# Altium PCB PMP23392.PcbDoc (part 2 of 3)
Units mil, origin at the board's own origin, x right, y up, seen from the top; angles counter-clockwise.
Board outline 5000 x 3400 mil, 6 copper layers (Top Layer, Midlayer 1, Midlayer 2, Midlayer 3, Midlayer 4, Bottom Layer), stack 61.536 mil thick; 247 components, 68 nets, 546 pads, 871 vias.
Unrouted connection lines stored in the file: 21.
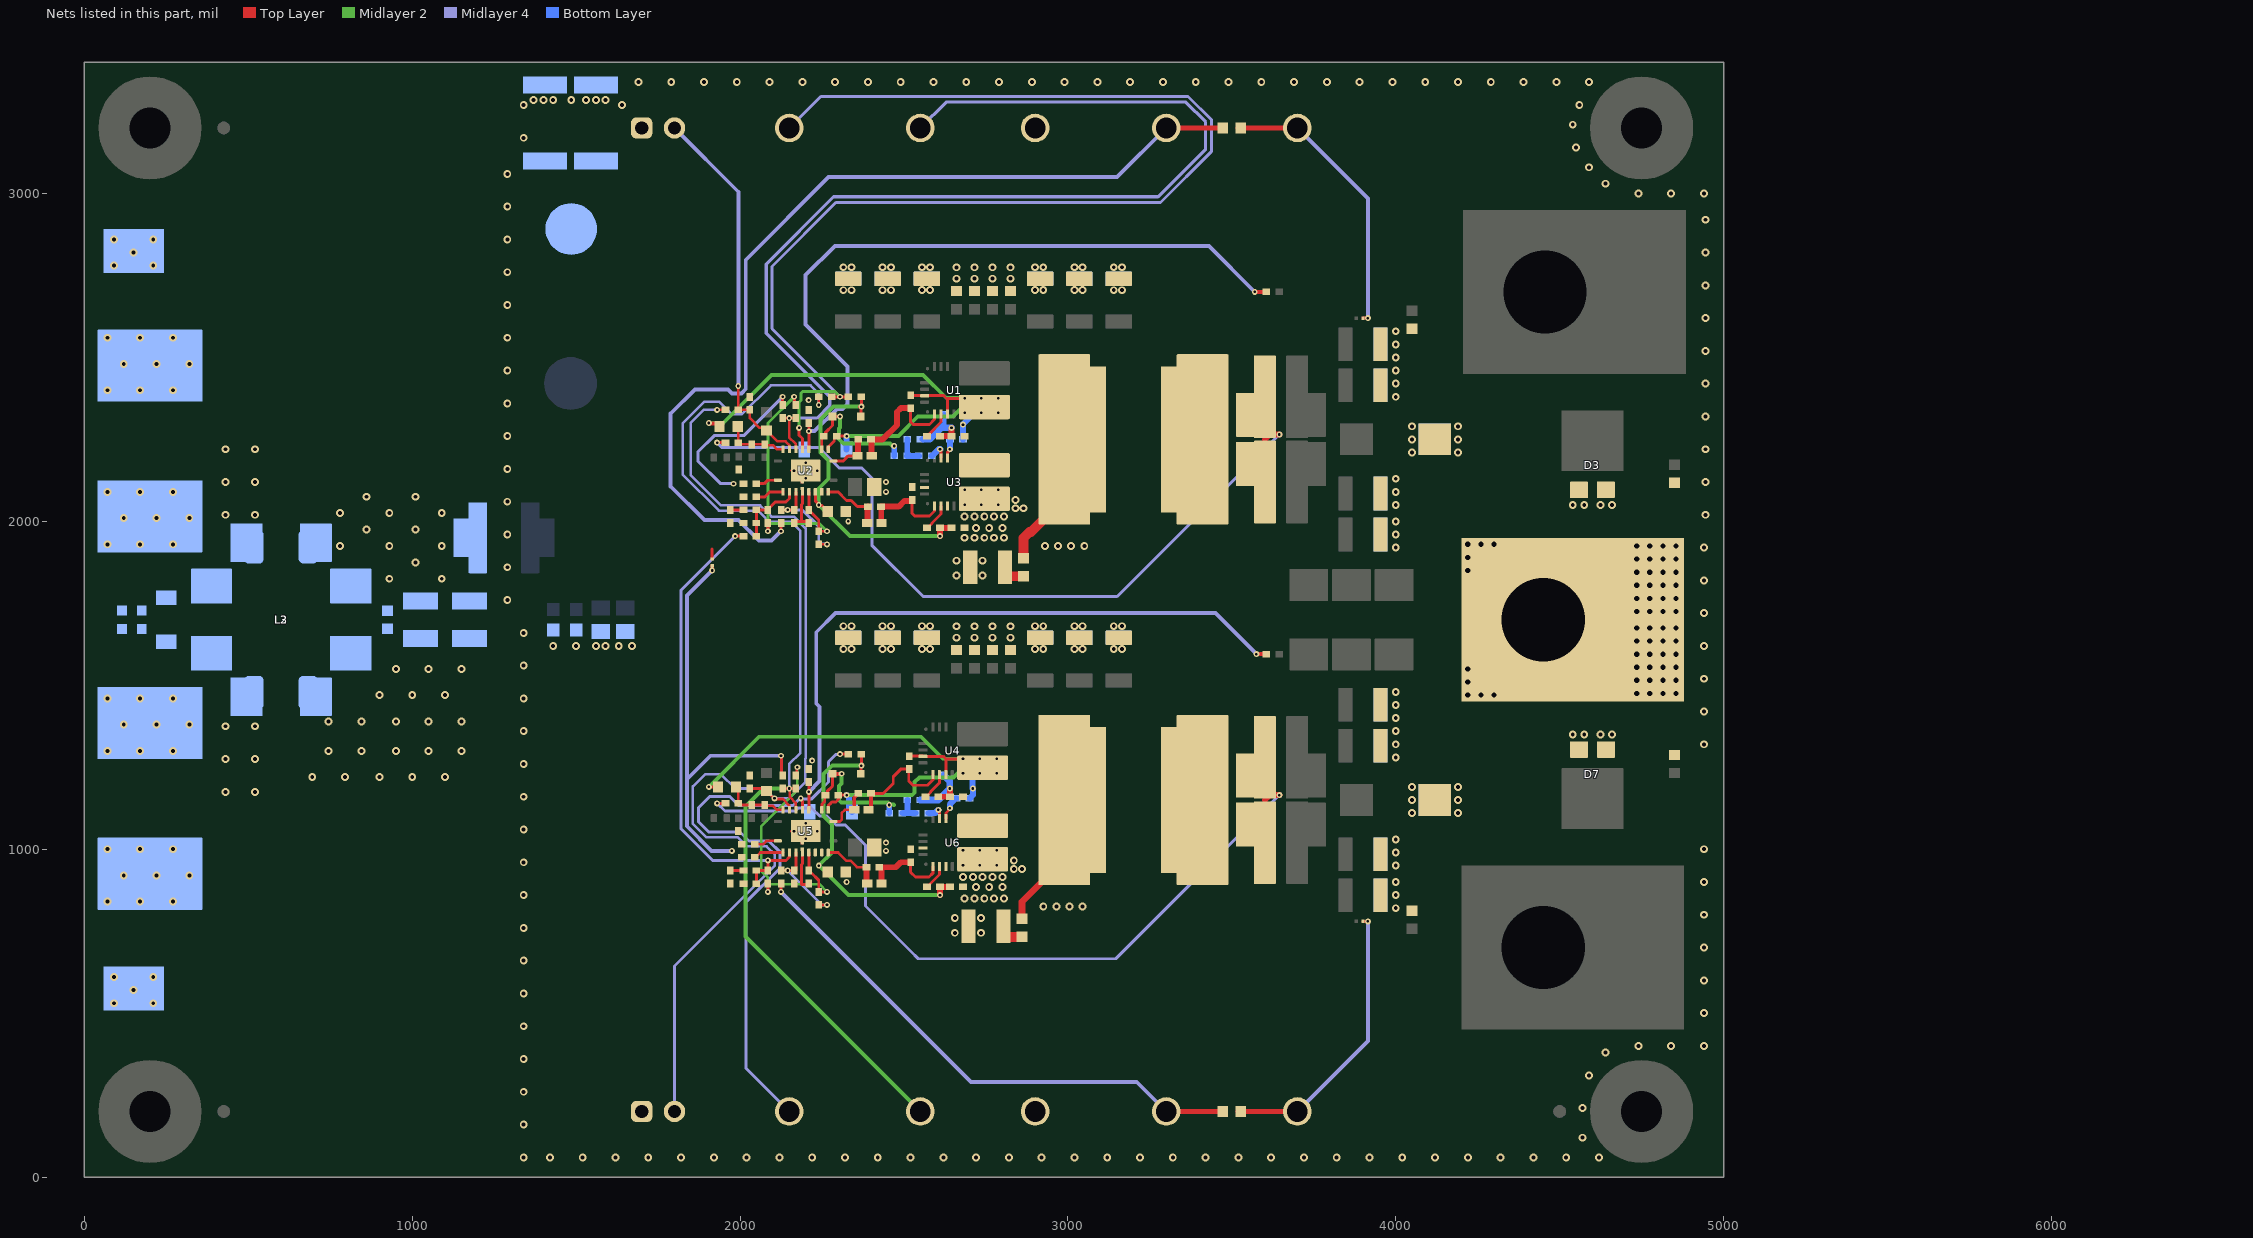
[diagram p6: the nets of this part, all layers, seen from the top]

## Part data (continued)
C52: library part CMP-0006353-2, "CAP, CERM, 0.022 uF, 25 V, +/- 10%, X7R, AEC-Q200 Grade 1, 0402", Cap_Case=0402, Manufacturer=MuRata, Supplier Part Number 1=490-6044-1-ND, TempCo=X7R, Tolerance_%=10%, Value1=Unknown, Value2=25V, ValueDisplayed=0.022uF
C53 C95: library part CMP-0006705-2, "CAP, CERM, 270 pF, 100 V, +/- 10%, X7R, 0402", Cap_Case=0402, Manufacturer=MuRata, Supplier Part Number 1=GRM155R72A271KA01D-ND, TempCo=X7R, Tolerance_%=10%, Value1=Unknown, Value2=100V, ValueDisplayed=270pF
C94: library part CMP-0006670-2, "CAP, CERM, 5600 pF, 25 V, +/- 10%, X7R, 0402", Cap_Case=0402, Manufacturer=MuRata, PartNumber=GRM155R71E562KA01D, Supplier Part Number 1=490-5420-1-ND, TempCo=X7R, Tolerance_%=10%, Value1=Unknown, Value2=25V, ValueDisplayed=5600pF
C96 C97 C98 C99: library part CMP-0025958-3, "RES, 10.0 k, 1%, 0.063 W, AEC-Q200 Grade 0, 0402", Manufacturer=Vishay-Dale, Power_W=63mW, Supplier Part Number 1=541-10.0KLCT-ND, TempCo="100 ppm/C", Tolerance_%=1%, Value2=0.063W, Value_Code=10k0, ValueDisplayed=10.0k
D1 D5: library part CMP-0076946-1, "Diode, Schottky, 100 V, 0.25 A, SOD-323F", Manufacturer=Nexperia, Supplier Part Number 1=568-6017-1-ND, Value1=0.25A, Value2=0.85V
D2 D6: library part Zener, "Diode, Zener, 5.6V, 2%, 500mW, SOD-323F", Alternate Manufacturer=-, Manufacturer=Nexperia
D3 D7: library part CMP-0048085-1, "Diode 40 V 10A Surface Mount TO-277A (SMPC)", Digikey Part Number=SS10P4HM3_A/HGICT-ND, Forward Current=10A, Manufacturer=Vishay, Max Surge Forward Current=280A, Mouser Part Number=78-SS10P4HM3_A/H, Operating Temperature Range="-55°C to +150°C", Peak Reverse Current=100uA, ValueDisplayed=750pF
D4 D8: library part Diode_Schottky, "Diode, Schottky, 100V, 2A, SOD-123", Alternate Manufacturer=-, Manufacturer=Nexperia, PartNumber=PMEG10020AELRX
D9 D10 D11 D12: library part Diode_Schottky, "Diode, Schottky, 30V, 200mA, SOD-523", Alternate Manufacturer=-, Manufacturer="ON Semi", PartNumber=NSVRB521S30T1G
FID1 FID2 FID3 FID4 FID5 FID6: library part CMP-0077181-1, "Fiducial mark.  There is nothing to buy or mount.", Manufacturer=N/A
H1 H2 H3 H4: library part CMP-0003617-1, "Machine Screw, Round, #4-40 x 1/4, Nylon, Philips panhead", Manufacturer="B&F Fastener Supply", Supplier Part Number 1=H542-ND
H5 H6 H7 H8: library part CMP-0003610-1, "Standoff, Hex, 0.5\"L #4-40 Nylon", Manufacturer=Keystone, Supplier Part Number 1=36-1902C-ND
J1 J2 J7 J9 J10 J11: library part CMP-0055135-1, "Shorting Jumper, 5.375mm, 2 Position, Tin, SMT", Color=Silver, Manufacturer=Keystone, PartNumber=5102, Supplier Part Number 1=36-5102-ND
J3 J4: library part CMP-0079575-1, "Banana Jack Insul Nylon Red, TH", Color=Red, Current_A=15A, Manufacturer="Cinch Connectivity", PartNumber=108-0902-001, Supplier Part Number 1=J151-ND
J5 J6: library part CMP-0079574-1, "Banana Jack Insul Nylon Black, TH", Color=Black, Current_A=15A, Manufacturer="Cinch Connectivity", PartNumber=108-0903-001, Supplier Part Number 1=J152-ND
J8 J12: library part CMP-0075405-3, "Header, 100mil, 2x1, Gold, TH", Color=Black, Current_A=6.3A, Manufacturer=Samtec, PartNumber=TSW-102-07-G-S, Supplier Part Number 1=SAM1029-02-ND, Voltage_V=550V
L1: library part CMP-0048360-1, "1 µH Shielded Molded Inductor 22 A 2.9mOhm Max Nonstandard", Digikey Part Number=2457-XGL6060-102MEC-ND, Manufacturer=Coilcraft, Operating Temperature Range=to, Part Number=XGL6060-102MEC, Self Resonant Frequency=46MHz, Test Frequency=1MHz, Tolerance_%=20%
L2: library part CMP-0084691-1, "Coupled inductor,  ohm, AEC-Q200 Grade 1, SMD", Manufacturer=TDK, PartNumber=ACM12V-701-2PL-TL00
L3: library part CMP-0013197-2, "Coupled inductor, 2 uH,  A, 1.8 ohm, SMD", Manufacturer=MuRata, PartNumber=PLT10HH101150PNL, Supplier Part Number 1=490-12821-1-ND, ValueDisplayed=2uH
L4 L6: library part CMP-0060945-1, "Inductor, Shielded, Composite, 1.5 uH, 36.6 A, 0.0016 ohm, SMD", Manufacturer=Coilcraft, Value1="0.0016 ohm", Value2=36.6A, ValueDisplayed=1.5uH
L5 L7: library part CMP-0047844-1, "Power Choke Coil 2.5uH 20% 100kHz 2.53mOhm 32A AECQ200 13.3x12.8x8.0mm SMT", Manufacturer=CYNTEC, Operating Temperature Range="-55°C to +180°C", Part Number=VCUD128T-2R5MS8, Test Frequency=100kHz, Tolerance_%=20%
LBL1: library part CMP-0003625-1, "Thermal Transfer Printable Labels, 0.650\" W x 0.200\" H - 10,000 per roll", Manufacturer=Brady, Supplier Part Number 1=97C5133
Logo1: library part CMP-0074844-1
Logo2: library part CMP-0074847-1, "FCC_disclaimer"
Logo3: library part CMP-0074769-1
NT1 NT2 NT3 NT4 NT5: library part CMP-0078142-3, "Single point connection between nets.", Manufacturer=N/A
R1 R2: library part CMP-0015904-3, "RES, 1.0, 5%, 1 W, AEC-Q200 Grade 0, 2512", Manufacturer=Vishay-Dale, Power_W=1W, Supplier Part Number 1=541-1.0XCT-ND, TempCo="200 ppm/C", Tolerance_%=5%, Value_Code=1R00, ValueDisplayed=1.0
R3 R4 R7 R21 R27 R28 R31 R32 R43 R47 R49: library part CMP-0081856-1, "RES, 0, 0%, 0.2 W, AEC-Q200 Grade 0, 0402", Manufacturer=Vishay-Dale, Power_W=200mW, Supplier Part Number 1=541-0.0YBTR-ND, Tolerance_%=0%, Value2=0.2W, Value_Code=0
R5 R30 R66 R67: library part CMP-0046355-1, "Res Current Sense Thick Film 1225 0.5m Ohm 5% 2W ±150ppm/°C Molded Emboss T/R", Digikey Part Number=RHM.0005BRCT-ND, Manufacturer="Rohm Semiconductor", Mouser Part Number=755-PML100HZPJV0L5, Operating Temperature Range="-55°C to +155°C", Part Number=PML100HZPJV0L5, Power_W=2W, TempCo=150ppm/°C, Tolerance_%=5%
R6: library part CMP-0022060-4, "RES, 150 k, 1%, 0.1 W, AEC-Q200 Grade 0, 0603", Manufacturer=Vishay-Dale, Power_W=100mW, Supplier Part Number 1=541-150KHCT-ND, TempCo="100 ppm/C", Tolerance_%=1%, Value2=0.1W, Value_Code=150k
R8 R33: library part CMP-0001672-1, "1.2 mOhms ±1% 5W Chip Resistor 2512 (6432 Metric) Automotive AEC-Q200, Current Sense, Non-Inductive Metal Element", Digikey Part Number=804-Y14830R00120F9RCT-ND, Manufacturer="Vishay Foil Resistors", Operating Temperature Range="-65°C to +170°C", Power_W=5W, Tolerance_%=1%
R9: library part CMP-0026517-2, "RES, 6.81 k, 1%, 0.063 W, AEC-Q200 Grade 0, 0402", Manufacturer=Vishay-Dale, Power_W=63mW, Supplier Part Number 1=541-6.81KLCT-ND, TempCo="100 ppm/C", Tolerance_%=1%, Value2=0.063W, Value_Code=6k81, ValueDisplayed=6.81k
R10 R19 R46 R50: library part CMP-0026753-1, "RES, 100 k, 1%, 0.063 W, AEC-Q200 Grade 0, 0402", Manufacturer="Stackpole Electronics Inc", PartNumber=RMCF0402FT100K, Power_W=63mW, Supplier Part Number 1=RMCF0402FT100KCT-ND, TempCo="100 ppm/C", Tolerance_%=1%, Value2=0.063W, Value_Code=100k
R11 R16 R36 R41: library part Resistor, "RES, xxx ohm, x%, xW, [PackageReference]", Alternate Manufacturer=-, Manufacturer="Used in BOM report"
R12 R37: library part CMP-0026404-2, "RES, 49.9, 1%, 0.063 W, AEC-Q200 Grade 0, 0402", Manufacturer=Vishay-Dale, Power_W=63mW, Supplier Part Number 1=541-49.9LCT-ND, TempCo="100 ppm/C", Tolerance_%=1%, Value2=0.063W, Value_Code=49R9, ValueDisplayed=49.9
R13 R38: library part CMP-0086542-2, "RMCF/RMCP Series General Purpose Thick Film Standard Power and High Power Chip Resistor", Manufacturer=Stackpole, TempCo=-, Value1=0
R14 R39: library part Resistor, "RES, 1.0 ohm, 5%, 0.5W, 1210", Alternate Manufacturer=-, Manufacturer=Stackpole, PartNumber=RMCF1210JT4R70
R15 R20 R40 R45 R58 R59 R60 R61 R62 R63: library part CMP-0081856-1, "RES, 0, 0%, 0.2 W, AEC-Q200 Grade 0, 0402", Manufacturer=Vishay-Dale, PartNumber=CRCW04020000Z0EDHP, Power_W=200mW, Supplier Part Number 1=541-0.0YBTR-ND, Tolerance_%=0%, Value2=0.2W, Value_Code=0
R17: library part CMP-0022448-4, "RES, 49.9, 1%, 0.1 W, AEC-Q200 Grade 0, 0603", Manufacturer=Vishay-Dale, Power_W=100mW, Supplier Part Number 1=541-49.9HCT-ND, TempCo="100 ppm/C", Tolerance_%=1%, Value2=0.1W, Value_Code=49R9, ValueDisplayed=49.9
R18 R44: library part CMP-0026539-2, "RES, 73.2 k, 1%, 0.063 W, AEC-Q200 Grade 0, 0402", Manufacturer=Vishay-Dale, Power_W=63mW, Supplier Part Number 1=541-73.2KLCT-ND, TempCo="100 ppm/C", Tolerance_%=1%, Value2=0.063W, Value_Code=73k2, ValueDisplayed=73.2k
R22: library part CMP-0026399-2, "RES, 48.7 k, 1%, 0.063 W, AEC-Q200 Grade 0, 0402", Manufacturer=Vishay-Dale, PartNumber=CRCW040248K7FKED, Power_W=63mW, Supplier Part Number 1=541-48.7KLCT-ND, TempCo="100 ppm/C", Tolerance_%=1%, Value2=0.063W, Value_Code=48k7, ValueDisplayed=48.7k
R23 R35: library part CMP-0026753-1, "RES, 100 k, 1%, 0.063 W, AEC-Q200 Grade 0, 0402", Manufacturer="Stackpole Electronics Inc", Power_W=63mW, Supplier Part Number 1=RMCF0402FT100KCT-ND, TempCo="100 ppm/C", Tolerance_%=1%, Value2=0.063W, Value_Code=100k
R24: library part CMP-0026329-2, "RES, 3.01 k, 1%, 0.063 W, AEC-Q200 Grade 0, 0402", Manufacturer=Vishay-Dale, Power_W=63mW, Supplier Part Number 1=541-3.01KLCT-ND, TempCo="100 ppm/C", Tolerance_%=1%, Value2=0.063W, Value_Code=3k01, ValueDisplayed=3.01k
R25: library part CMP-0026449-2, "RES, 54.9 k, 1%, 0.063 W, AEC-Q200 Grade 0, 0402", Manufacturer=Vishay-Dale, Power_W=63mW, Supplier Part Number 1=541-54.9KLCT-ND, TempCo="100 ppm/C", Tolerance_%=1%, Value2=0.063W, Value_Code=54k9, ValueDisplayed=54.9k
R26: library part CMP-0026067-3, "RES, 19.1 k, 1%, 0.063 W, AEC-Q200 Grade 0, 0402", Manufacturer=Vishay-Dale, Power_W=63mW, Supplier Part Number 1=541-19.1KLCT-ND, TempCo="100 ppm/C", Tolerance_%=1%, Value2=0.063W, Value_Code=19k1, ValueDisplayed=19.1k
R29: library part CMP-0021990-4, "RES, 100 k, 1%, 0.1 W, AEC-Q200 Grade 0, 0603", Manufacturer=Vishay-Dale, PartNumber=CRCW0603100KFKEA, Power_W=100mW, Supplier Part Number 1=541-100KHCT-ND, TempCo="100 ppm/C", Tolerance_%=1%, Value2=0.1W, Value_Code=100k
R34: library part CMP-0026412-2, "RES, 4.75 k, 1%, 0.063 W, AEC-Q200 Grade 0, 0402", Manufacturer=Vishay-Dale, PartNumber=CRCW04024K75FKED, Power_W=63mW, Supplier Part Number 1=541-4.75KLCT-ND, TempCo="100 ppm/C", Tolerance_%=1%, Value2=0.063W, Value_Code=4k75, ValueDisplayed=4.75k
R42: library part CMP-0022448-4, "RES, 49.9, 1%, 0.1 W, AEC-Q200 Grade 0, 0603", Manufacturer=Vishay-Dale, PartNumber=CRCW060349R9FKEA, Power_W=100mW, Supplier Part Number 1=541-49.9HCT-ND, TempCo="100 ppm/C", Tolerance_%=1%, Value2=0.1W, Value_Code=49R9, ValueDisplayed=49.9
R48: library part CMP-0026555-2, "RES, 7.50 k, 1%, 0.063 W, AEC-Q200 Grade 0, 0402", Manufacturer=Vishay-Dale, PartNumber=CRCW04027K50FKED, Power_W=63mW, Supplier Part Number 1=541-7.50KLCT-ND, TempCo="100 ppm/C", Tolerance_%=1%, Value2=0.063W, Value_Code=7k50, ValueDisplayed=7.50k
R51 R53: library part CMP-0086542-2, "RMCF/RMCP Series General Purpose Thick Film Standard Power and High Power Chip Resistor", Manufacturer=Stackpole, PartNumber=RMCF0402ZT0R00, TempCo=-
R52: library part CMP-0026605-2, "RES, 90.9 k, 1%, 0.063 W, AEC-Q200 Grade 0, 0402", Manufacturer=Vishay-Dale, Power_W=63mW, Supplier Part Number 1=541-90.9KLCT-ND, TempCo="100 ppm/C", Tolerance_%=1%, Value2=0.063W, Value_Code=90k9, ValueDisplayed=90.9k
R54 R55 R56 R57: library part CMP-0026357-2, "RES, 3.32, 1%, 0.063 W, AEC-Q200 Grade 0, 0402", Manufacturer=Vishay-Dale, Power_W=63mW, Supplier Part Number 1=541-3.32LLCT-ND, TempCo="100 ppm/C", Tolerance_%=1%, Value2=0.063W, Value_Code=3R32, ValueDisplayed=3.32
R64 R65: library part CMP-0001672-1, "1.2 mOhms ±1% 5W Chip Resistor 2512 (6432 Metric) Automotive AEC-Q200, Current Sense, Non-Inductive Metal Element", Digikey Part Number=804-Y14830R00120F9RCT-ND, Manufacturer="Vishay Foil Resistors", Operating Temperature Range="-65°C to +170°C", Part Number=Y14830R00120F9R, Power_W=5W, Tolerance_%=1%
SH-J1 SH-J2: library part CMP-0003761-2, "Shunt, 2.54mm, Gold, Black", Manufacturer="Wurth Elektronik", Supplier Part Number 1=732-2678-ND
T1 T2 T3: library part CMP-0055443-2, "Terminal 90A Lug", Manufacturer=Panduit, PartNumber=CB70-14-CY, Supplier Part Number 1=CB70-14-CY-ND, Voltage_V=600V
TP1 TP2: library part CMP-0055153-2, "Test Point, Compact, SMT", Manufacturer="Keystone Electronics", PartNumber=5016, Supplier Part Number 1=36-5016TR-ND
TP3 TP9: library part CMP-0055147-1, "Test Point, Multipurpose, Red, TH", Color=Red, Manufacturer=Keystone, PartNumber=5010, Supplier Part Number 1=36-5010-ND
TP4 TP5 TP6 TP10 TP11 TP12: library part CMP-0055149-1, "Test Point, Multipurpose, White, TH", Color=White, Manufacturer=Keystone, PartNumber=5012, Supplier Part Number 1=36-5012-ND
TP7 TP8: library part CMP-0055148-1, "Test Point, Multipurpose, Black, TH", Color=Black, Manufacturer=Keystone, PartNumber=5011, Supplier Part Number 1=36-5011-ND
U1 U3 U4 U6: library part CMP-0037654-1, "100-V, 64-A GaN with Integrated Driver", Manufacturer="Texas Instruments", Max Supply Voltage=5.25V, Min Supply Voltage=4.75V, Nominal Supply Current=3mA, Operating Temperature Range="-40°C to +125°C"
U2 U5: library part CMP-0120564-1, "80-V, Automotive, Synchronous, Buck DC/DC Controller with Ultra-Low IQ and Dual Random Spread Spectrum", Manufacturer="Texas Instruments", Max Supply Voltage=80V, Min Supply Voltage=3.5V, Nominal Supply Current=9.5-124uA, Operating Temperature Range="-40°C to +150°C", Output Voltage=3.3/5/12/0.8-55V, Switching Frequency=0.1-2.2MHz

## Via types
v1: diameter 24, hole 12, Top Layer to Bottom Layer, tented both sides, 526 vias
v2: diameter 32, hole 16, Top Layer to Bottom Layer, 174 vias
v3: diameter 18, hole 8, Top Layer to Bottom Layer, tented both sides, 77 vias
v4: diameter 24, hole 12, Top Layer to Bottom Layer, 46 vias
v5: diameter 19.68, hole 7.87, Top Layer to Bottom Layer, tented both sides, 44 vias
v6: diameter 19.68, hole 7.87, Top Layer to Bottom Layer, tented bottom, 4 vias

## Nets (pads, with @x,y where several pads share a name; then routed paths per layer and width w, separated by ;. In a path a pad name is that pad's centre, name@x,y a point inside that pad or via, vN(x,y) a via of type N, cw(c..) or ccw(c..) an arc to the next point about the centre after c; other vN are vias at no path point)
+Filter: C5.2 C6.2 C7.1 J1.2 J2.1 L1.2 L2.3 L3.3
  other v1: 930,1825 1090,1825 1010,1875 780,1925 930,1925 1090,1925 860,1975 1010,1975 780,2025 930,2025 1090,2025 860,2075 1010,2075
+Vin_Main: C2.1 C3.1 C4.1 J2.2 J3.1 J4.1 L2.2 L3.4 TP1.1
  other v1: 430,2020 520,2020 430,2120 520,2120 430,2220 520,2220
  other v4: 70,1930 170,1930 270,1930 120,2010 220,2010 320,2010 70,2090 170,2090 270,2090 70,2400 170,2400 270,2400 120,2480 220,2480 320,2480 70,2560 170,2560 270,2560 90,2780 210,2780 150,2820 90,2860 210,2860
AGND1: C33.1 C51.2 C52.2 NT2.2 NT3.1 R18.2 R20.2 R25.1 R26.1 U2.5 | length 689.6
  Top Layer w9: NT3.1@1915,1885 1915,1915.76 ; R20.2@2130,2354.69 v3(2130,2380) ; R26.1@2165,1995.32 2169.96,2000.27 2187.22,2000.27 ; U2.5@2190.16,2090.04 2190.16,2054 2187.22,2051.05 2187.22,2000.27 ; C33.1@2210,1995.32 2205.04,2000.27 2187.22,2000.27
  Midlayer 4 w9: v3(1980.16,2114.84) 1940.75,2114.84 1871.25,2184.34 1871.25,2211.48 1921.15,2261.37 2011.37,2261.37 v3(2130,2380)
AGND2: C75.1 C93.2 C94.2 NT3.2 NT5.2 R44.2 R45.2 R52.1 R53.2 U5.5 | length 1496.5
  Top Layer w9: v3(2125,1285) 2126.72,1283.28 2126.72,1227.96 R45.2@2130,1224.69 ; U5.5@2190.16,990.04 2190.16,955.73 2187.22,952.79 2187.22,892.26 2205.22,892.26 C75.1@2209.69,896.73
  Top Layer w10: v3(1915,1850) NT3.2@1915,1865
  Midlayer 4 w12: v3(1915,1850) 1838.37,1773.37 1838.37,1213.37 ; v3(1975,995) 1913.33,995 1838.37,1069.96 1838.37,1213.37 ; v3(2125,1285) 1910,1285 1838.37,1213.37
Bode1: R17.1 R23.2 TP6.1 | length 2958
  Top Layer w9: v3(2125,1970) R23.2@2125,1995.31
  Top Layer w16: TP6.1@3300,3200 R17.1@3480.31,3200
  Midlayer 4 w12: v3(2125,1970) 2096.22,1941.22 2057.56,1941.22 1994.57,2004.21 1891.24,2004.21 1788.46,2106.99 1788.46,2328.46 1862.61,2402.61 1963.37,2402.61 1975.98,2390 2004.04,2390 2017.44,2403.4 2017.44,2797.44 2270,3050 3150,3050 TP6.1@3300,3200
Bode2: R42.1 R50.2 TP12.1 | length 1658.2
  Top Layer w9: v3(2125,870) R50.2@2125,895.31
  Top Layer w16: TP12.1@3300,200 R42.1@3480.31,200
  Midlayer 4 w12: v3(2125,870) 2705,290 3210,290 TP12.1@3300,200
CNFG1: R25.2 U2.1 | length 70
  Top Layer w9: R25.2@2049.69,2115 2073.69,2115 2084.16,2125.47 U2.1@2115.35,2125.47
CNFG2: R52.2 U5.1 | length 75
  Top Layer w8: R52.2@2044.69,1015 2070,1015 2080.47,1025.47 U5.1@2115.35,1025.47
COMP1: C51.1 R19.1 R24.2 R49.2 U2.3 | length 217.1
  Top Layer w9: R49.2@2049.69,1955 C51.1@2049.68,1995 R24.2@2049.69,2035 2049.84,2034.84 2084.84,2034.84 R19.1@2085,2034.68 2085,2036.65 2107.22,2058.87 2139.66,2058.87 2150.79,2070 U2.3@2150.79,2090.04
COMP2: C93.1 R46.2 R48.2 R49.1 U5.3 | length 1482.6
  Top Layer w9: v3(1985,1955) R49.1@2010.32,1955 ; C93.1@2049.68,895 R48.2@2049.69,935 2049.84,934.84 2084.84,934.84 R46.2@2085,934.69 v3(2085,966.04) 2085.18,965.85 2140,965.85 2150.37,976.22 2150.37,989.62 U5.3@2150.79,990.04
  Midlayer 4 w9: v3(1985,1955) 1820,1790 1820,1062.35 1917.35,965 2083.96,965 v3(2085,966.04)
EN1: J8.2 R6.1 R9.2 R32.2 U2.17 | length 1168.6
  Top Layer w8: v3(1994.57,2412.87) 1994.63,2412.81 1994.63,2342.19 R32.2@1996.65,2340.16 ; R32.2@1994.69,2340 1996.5,2340 R32.2@1996.65,2340.16 ; U2.17@2150.79,2219.96 2149.87,2220.88 2149.87,2233.57 2139.15,2244.28 2114.14,2244.28 2080.98,2277.44 R6.1@2080,2277.44 2072.13,2285.31 2059.33,2285.31 2030,2314.65 2030,2338.35 2028.19,2340.16 R32.2@1996.65,2340.16
  Midlayer 4 w12: J8.2@1800,3200 1994.57,3005.43 v3(1994.57,2412.87)
EN2: J12.2 R29.1 R32.1 R34.2 U5.17 | length 3350.4
  Top Layer w8: v3(1930,2340) R32.1@1955.32,2340 ; R34.2@2030,1185.31 2072.13,1185.31 R29.1@2080,1177.44 2080.98,1177.44 2103.43,1155 v3(2105,1155) 2106.91,1153.09 2130.35,1153.09 2149.87,1133.57 2149.87,1120.88 U5.17@2150.79,1119.96
  Midlayer 4 w8: J12.2@1800,200 1800,643.78 2105.87,949.65 2105.87,983.65 2080.69,1008.83 2020.18,1008.83 1993.14,1035.87 1897.74,1035.87 1856.25,1077.36 1856.25,1191.25 1893.37,1228.37 1942.3,1228.37 1985.36,1185.31 2074.69,1185.31 v3(2105,1155) 2149.52,1155 2199.13,1204.61 2199.13,1275.98 2200,1276.86 2200,1978.35 2164.22,2014.13 2095.87,2014.13 2061.22,2048.78 1941.89,2048.78 1850,2140.67 1850,2301.1 1888.9,2340 v3(1930,2340)
FB1: R22.2 R23.1 R26.2 U2.4 | length 312.6
  Top Layer w9: R23.1@2125,2034.68 R26.2@2165,2034.69 2170.34,2040.03 2170.34,2064.6 2170.47,2064.73 U2.4@2170.47,2090.04 ; R22.2@2240,1930.31 2240.16,1930.16 2264.84,1930.16 v3(2265,1930)
  Midlayer 4 w9: v3(2145,2035) 2190,2035 2240,1985 2240,1940 2248.28,1931.72 2263.28,1931.72 v3(2265,1930)
FB2: R50.1 R51.2 R53.1 U5.4 | length 284
  Top Layer w9: R50.1@2125,934.68 2145,934.69 R53.1@2165,934.69 ; R53.1@2170.34,934.69 2170.34,955.78 2170.47,955.91 U5.4@2170.47,990.04 ; R51.2@2240,830.31 2240.16,830.16 2264.84,830.16 v3(2265,830)
  Midlayer 4 w9: v3(2145,935) 2250,830 v3(2265,830)
GND: C5.1 C6.1 C7.2 C8.2 C9.2 C10.2 C11.2 C12.1 C13.1 C14.1 C15.1 C16.1 C17.2 C18.2 C19.2 C20.2 C21.1 C22.1 C23.1 C24.1 C25.2 C26.2 C27.2 C28.2 C29.1 C30.2 C34.2 C36.2 C37.2 C38.2 C39.2 C40.2 C41.2 C42.2 C43.2 C44.2 C45.2 C46.2 C47.2 C48.1 C50.2 C53.1 C54.1 C55.1 C56.1 C57.1 C58.1 C59.2 C60.2 C61.2 C62.2 C63.1 C64.1 C65.1 C66.1 C67.1 C68.2 C69.2 C70.2 C71.2 C72.2 C76.2 C78.2 C79.2 C80.2 C81.2 C82.2 C83.2 C84.2 C85.2 C86.2 C87.2 C88.2 C89.2 C90.1 C92.2 C95.1 C97.1 C99.1 C100.1 C101.1 C102.1 C103.1 D3.1 D3.2 D4.2 D7.1 D7.2 D8.2 J7.1 J8.1 J12.1 L2.4 L3.2 NT2.1 NT5.1 R1.1 R2.1 R9.1 R14.1 R34.1 R39.1 T2.1 TP7.1 TP8.1 U2.8 U2.20 U3.4 U3.6 U3.14 U5.8 U5.20 U6.4 U6.6 U6.14 | length 103.3
  Top Layer w10: U5.20@2156.69,1055 2161.54,1055 2190,1026.54 NT5.1@2190,1020 ; U2.20@2156.69,2155 2161.54,2155 2190,2126.54 NT2.1@2190,2120
  other v1: 1340,60 1420,60 1520,60 1620,60 1720,60 1820,60 1920,60 2020,60 2120,60 2220,60 2320,60 2420,60 2520,60 2620,60 2720,60 2820,60 2920,60 3020,60 3120,60 3220,60 3320,60 3420,60 3520,60 3620,60 3720,60 3820,60 3920,60 4020,60 4120,60 4220,60 4320,60 4420,60 4520,60 4620,60 4570,120 1340,160 4570,210 1340,260 4590,310 1340,360 4640,380 4740,400 4840,400 4940,400 1340,460 4940,500 1340,560 4940,600 1340,660 4940,700 2655,745 2735,745 1340,760 2655,790 2735,790 4940,800 4000,820 2925,825 2965,825 3005,825 3045,825 2685,850 2715,850 2745,850 2775,850 2805,850 1340,860 4000,860 2720,885 2760,885 2800,885 4000,900 4940,900 2680,915 2710,915 2740,915 2770,915 2800,915 2835,940 2860,940 4000,950 1340,960 2835,965 4000,990 4940,1000 4000,1030 1340,1060 4050,1110 4190,1110 4050,1150 4190,1150 1340,1160 4050,1190 4190,1190 695,1220 795,1220 900,1220 1000,1220 1100,1220 1340,1260 4000,1280 745,1300 845,1300 950,1300 1050,1300 1150,1300 4000,1320 4940,1320 4540,1350 4575,1350 4625,1350 4660,1350 1340,1360 4000,1360 745,1390 845,1390 950,1390 1050,1390 1150,1390 4000,1400 4940,1420 4000,1440 1340,1460 900,1470 1000,1470 1100,1470 4000,1480 4940,1520 950,1550 1050,1550 1150,1550 1340,1560 2314.87,1610.18 2339.87,1610.18 2434.87,1610.18 2459.87,1610.18 2554.87,1610.22 2579.87,1610.22 2899.87,1610.22 2924.87,1610.22 3019.87,1610.22 3044.87,1610.22 3139.87,1610.18 3164.87,1610.18 1430,1620 1500,1620 1560,1620 1590,1620 1630,1620 1670,1620 4940,1620 2659.87,1645.18 2714.87,1645.18 2769.87,1645.18 2824.87,1645.18 1340,1660 2314.87,1680.18 2339.87,1680.18 2434.87,1680.18 2459.87,1680.18 2554.87,1680.22 2579.87,1680.22 2660,1680 2715,1680 2770,1680 2825,1680 2899.87,1680.22 2924.87,1680.22 3019.87,1680.22 3044.87,1680.22 3139.87,1680.18 3164.87,1680.18 4940,1720 1290,1760 4940,1820 2660,1835 2740,1835 1290,1860 2660,1880 2740,1880 4000,1920 4940,1920 2930,1925 2970,1925 3010,1925 3050,1925 2685,1950 2715,1950 2745,1950 2775,1950 2805,1950 1290,1960 4000,1960 2720,1980 2760,1980 2800,1980 4000,2000 2685,2015 2715,2015 2745,2015 2775,2015 2805,2015 4945,2020 2840,2040 2865,2040 4000,2050 4540,2050 4575,2050 4625,2050 4660,2050 1290,2060 2840,2065 4000,2090 4945,2120 4000,2130 1290,2160 4050,2210 4190,2210 4945,2220 4050,2250 4190,2250 1290,2260 4050,2290 4190,2290 4945,2320 1290,2360 4000,2380 4000,2420 4945,2420 1290,2460 4000,2460 4000,2500 4945,2520 4000,2540 1290,2560 4000,2580 4945,2620 1290,2660 2314.87,2705.18 2339.87,2705.18 2434.87,2705.18 2459.87,2705.18 2554.87,2705.22 2579.87,2705.22 2899.87,2705.22 2924.87,2705.22 3019.87,2705.22 3044.87,2705.22 3139.87,2705.18 3164.87,2705.18 4945,2720 2659.87,2740.18 2714.87,2740.18 2769.87,2740.18 2824.87,2740.18 1290,2760 2314.87,2775.18 2339.87,2775.18 2434.87,2775.18 2459.87,2775.18 2554.87,2775.22 2579.87,2775.22 2660,2775 2715,2775 2770,2775 2825,2775 2899.87,2775.22 2924.87,2775.22 3019.87,2775.22 3044.87,2775.22 3139.87,2775.18 3164.87,2775.18 4945,2820 1290,2860 4945,2920 1290,2960 4740,3000 4840,3000 4940,3000 4640,3030 1290,3060 4590,3080 4550,3140 1340,3170 4540,3210 1340,3270 1640,3270 4560,3270 1370,3285 1400,3285 1430,3285 1485,3285 1530,3285 1560,3285 1590,3285 1690,3340 1790,3340 1890,3340 1990,3340 2090,3340 2190,3340 2290,3340 2390,3340 2490,3340 2590,3340 2690,3340 2790,3340 2890,3340 2990,3340 3090,3340 3190,3340 3290,3340 3390,3340 3490,3340 3590,3340 3690,3340 3790,3340 3890,3340 3990,3340 4090,3340 4190,3340 4290,3340 4390,3340 4490,3340 4590,3340
  other v2: 4220,1470 4260,1470 4300,1470 4735,1475 4775,1475 4815,1475 4855,1475 4220,1510 4735,1515 4775,1515 4815,1515 4855,1515 4220,1550 4735,1555 4775,1555 4815,1555 4855,1555 4735,1595 4775,1595 4815,1595 4855,1595 4735,1635 4775,1635 4815,1635 4855,1635 4735,1675 4775,1675 4815,1675 4855,1675 4735,1725 4775,1725 4815,1725 4855,1725 4735,1765 4775,1765 4815,1765 4855,1765 4735,1805 4775,1805 4815,1805 4855,1805 4735,1845 4775,1845 4815,1845 4855,1845 4220,1850 4735,1885 4775,1885 4815,1885 4855,1885 4220,1890 4735,1925 4775,1925 4815,1925 4855,1925 4220,1930 4260,1930 4300,1930
  other v3: 2325,900 2445,995 2445,1020 2220,1270 2330,2000 2445,2090 2445,2120 2209,2370
  other v5: 2680,951.38 2731.18,951.38 2782.36,951.38 2680,996.26 2731.18,996.26 2782.36,996.26 2200,1031.38 2164.57,1055 2235.43,1055 2200,1078.62 2685,2051.1 2736.18,2051.1 2787.36,2051.1 2685,2095.98 2736.18,2095.98 2787.36,2095.98 2200,2131.38 2164.57,2155 2235.43,2155 2200,2178.62
GNDin: C2.2 C3.2 C4.2 J5.1 J6.1 J7.2 L2.1 L3.1 TP2.1
  other v1: 430,1175 520,1175 430,1275 520,1275 430,1375 520,1375
  other v4: 90,530 210,530 150,570 90,610 210,610 70,840 170,840 270,840 120,920 220,920 320,920 70,1000 170,1000 270,1000 70,1300 170,1300 270,1300 120,1380 220,1380 320,1380 70,1460 170,1460 270,1460
HO1: D9.2 R54.1 U2.11 | length 131
  Top Layer w9: U2.11@2284.65,2184.53 2314.8,2184.53 2330.28,2200 D9.2@2358.35,2200
  Top Layer w18: D9.2@2358.35,2200 2359.33,2200.98 2359.33,2249.16 2360.17,2250 R54.1@2360.31,2250
HO1_GAN: C96.2 D9.1 R54.2 U1.2 | length 373.4
  Top Layer w9: C96.2@2520,2345.31 2520,2304.18 2528.34,2295.84 2577.5,2295.84 2593.04,2311.38 U1.2@2593.04,2326.74
  Top Layer w18: R54.2@2399.69,2250 R54.2@2399.83,2250 ; D9.1@2401.65,2200 2400.67,2200.98 2400.67,2249.16 R54.2@2399.83,2250 ; C96.2@2520,2345.31 2490.31,2345.31 2478.5,2333.5 2478.5,2293.6 2434.9,2250 R54.2@2399.83,2250
HO2: D11.2 R56.1 U5.11 | length 146.3
  Top Layer w8: U5.11@2284.65,1084.53 2304.97,1084.53 2310,1089.56 2310,1109.78 2320.22,1120 D11.2@2348.35,1120
  Top Layer w12: D11.2@2348.35,1120 2348.35,1158.03 2354.5,1164.19 2354.5,1166.16 2358.35,1170 R56.1@2360.31,1170
HO2_GAN: C98.2 D11.1 R56.2 U4.2 | length 351.1
  Top Layer w9: R56.2@2399.69,1170 2436.5,1170 2467.29,1200.79 2467.29,1221.26 2491.35,1245.32 C98.2@2515,1245.32 ; C98.2@2514.52,1244.84 2514.52,1207.81 2527.33,1195 2571.66,1195 2588.04,1211.38 U4.2@2588.04,1226.74
  Top Layer w12: D11.1@2391.65,1120 2393.87,1120 2399.69,1125.81 R56.2@2399.69,1170
ISNS+1: C49.2 R11.1 R12.1 R16.2 U2.18 | length 199.8
  Top Layer w8: R12.1@1992.56,2245 R12.1@1994.68,2242.87 ; R11.1@1992.56,2290 1994.68,2287.87 R12.1@1994.68,2242.87 ; R12.1@1994.68,2240 R12.1@1994.68,2242.87 ; U2.18@2131.1,2219.96 2112.45,2219.96 2100,2232.41 2077.27,2232.41 C49.2@2075,2234.69 R16.2@2035,2234.69 2002.87,2234.69 R12.1@1994.68,2242.87
ISNS+2: C91.2 R36.1 R37.1 R41.2 U5.18 | length 187.3
  Top Layer w8: R36.1@1987.56,1190 1994.68,1182.87 R37.1@1994.68,1140 ; R37.1@2002.87,1134.69 R41.2@2035,1134.69 C91.2@2075,1134.69 2077.27,1132.41 2100,1132.41 2112.45,1119.96 U5.18@2131.1,1119.96
LO1: D10.2 R55.1 U2.9 | length 190.8
  Top Layer w9: U2.9@2268.9,2090.04 2298.72,2090.04 2325.07,2063.69 2338.85,2063.69 2357.54,2045 R55.1@2390.17,2045
  Top Layer w18: D10.2@2388.35,1995 2389.33,1995.98 2389.33,2044.16 2390.17,2045 R55.1@2390.31,2045
LO1_GAN: C97.2 D10.1 R55.2 U3.2 | length 287.6
  Top Layer w9: C97.2@2525,2063.46 2525,2024.08 2532.5,2016.58 2578.24,2016.58 2593.04,2031.38 U3.2@2593.04,2046.74
  Top Layer w18: R55.2@2429.69,2045 R55.2@2429.83,2045 ; D10.1@2431.65,1995 2430.67,1995.98 2430.67,2044.16 R55.2@2429.83,2045 ; C97.2@2525,2065.32 2525,2063.46 2524.16,2062.61 2501.46,2062.61 2483.84,2045 R55.2@2429.83,2045
LO2: D12.2 R57.1 U5.9 | length 186.3
  Top Layer w8: U5.9@2268.9,990.04 2299.45,990.02 2325.27,964.2 2337.63,964.2 2356.83,945 R57.1@2385.31,945 ; D12.2@2385.31,898.03 D12.2@2388.35,895
  Top Layer w18: D12.2@2385.31,898.03 R57.1@2385.31,945
LO2_GAN: C99.2 D12.1 R57.2 U6.2 | length 274.6
  Top Layer w9: C99.2@2520,960.32 2520,929.84 2535,914.84 2576.51,914.84 2588.04,926.37 U6.2@2588.04,946.74
  Top Layer w18: R57.2@2424.69,945 2475.31,945 2490.63,960.32 C99.2@2520,960.32 ; D12.1@2431.65,895 R57.2@2431.65,938.03
NetC1_1: C1.1 R1.2 R2.2
NetC31_1: C31.1 D2.1 R3.1 R4.1 | length 205.1
  Top Layer w18: R3.1@2609.84,2259.84 2619.84,2259.84 2620,2260 C31.1@2645.31,2260 2645,2260.31 v3(2645,2285)
  Bottom Layer w20: R4.1@2557.56,2250 2578.31,2250 2615,2286.69 ; D2.1@2621.69,2325 2619.88,2323.19 2619.88,2291.57 2615,2286.69 ; v3(2645,2285) 2616.69,2285 2615,2286.69
NetC35_2: C35.2 R14.2 | length 57.9
  Top Layer w30: R14.2@2808.15,1860 R14.2@2810.71,1857.44 ; R14.2@2810.71,1832.44 C35.2@2865,1832.44
NetC52_1: C52.1 R24.1 | length 40.4
  Top Layer w9: C52.1@1970,2034.68 1970.16,2034.84 2010.16,2034.84 R24.1@2010.32,2035
NetC73_1: C73.1 D6.1 R27.1 R28.1 | length 213.2
  Top Layer w12: R27.1@2604.69,1160 R27.1@2604.84,1159.84
  Top Layer w18: R27.1@2604.84,1159.84 2619.84,1159.84 ; 2619.84,1160 C73.1@2640.31,1160 2640,1160.32 v3(2640,1185)
  Bottom Layer w20: R28.1@2549.69,1150 2605,1150 v3(2640,1185) 2640,1206.69 D6.1@2621.69,1225
NetC77_2: C77.2 R39.2 | length 57.9
  Top Layer w20: R39.2@2803.15,765 R39.2@2805.59,767.44
  Top Layer w30: R39.2@2805.59,732.44 C77.2@2860,732.44
NetC94_1: C94.1 R48.1 | length 40.4
  Top Layer w9: C94.1@1970,934.68 1970.16,934.84 2010.16,934.84 R48.1@2010.32,935
NetL4_2: L4.2 L5.2 R5.1 R8.1 R12.2 R64.1 R66.1 | length 2310.3
  Top Layer w9: v3(1930,2240) R12.2@1953.35,2240
  Top Layer w12: R12.2@1953.35,2240 R12.2@1955.31,2240
  Top Layer w18: 3600.79,2250 3615.79,2265 v3(3645,2265)
  Midlayer 4 w9: v3(1930,2240) 1944.13,2225.87 2239.36,2225.87 2301.98,2163.25 2370.77,2163.25 2402.03,2131.99 2402.03,1926.84 2558.44,1770.43 3150.43,1770.43 v3(3645,2265)
NetL6_2: L6.2 L7.2 R30.1 R33.1 R37.2 R65.1 R67.1 | length 2309.7
  Top Layer w9: v3(1930,1140) R37.2@1955.31,1140
  Top Layer w18: 3600.79,1150 3615.79,1165 v3(3645,1165)
  Midlayer 4 w9: v3(1930,1140) 1930.65,1140 1953.89,1116.75 2168.18,1116.75 2177.29,1125.87 2218.12,1125.87 2242.77,1101.22 2265.19,1101.22 2292.92,1073.49 2321.03,1073.49 2382.54,1011.99 2382.54,827.11 2519.83,689.83 2543.8,665.85 3145.85,665.85 v3(3645,1165)
NetNT1_1: NT1.1 R17.2 TP3.1 | length 864.4
  Top Layer w9: NT1.1@3900,2620 v3(3915,2620)
  Top Layer w16: R17.2@3519.69,3200 TP3.1@3700,3200
  Midlayer 4 w12: TP3.1@3700,3200 3915,2985 v3(3915,2620)
NetNT4_1: NT4.1 R42.2 TP9.1 | length 864.4
  Top Layer w9: NT4.1@3900,780 v3(3915,780)
  Top Layer w16: R42.2@3519.69,200 TP9.1@3700,200
  Midlayer 4 w12: TP9.1@3700,200 3915,415 v3(3915,780)
NetR3_2: R3.2 U1.3 | length 86.1
  Top Layer w9: R3.2@2570.31,2260 2572.28,2260 2577.63,2265.34 2577.63,2267.31 2613.15,2302.83 U1.3@2613.15,2327.17
NetR4_2: R4.2 R58.2 R63.1 | length 85.9
  Bottom Layer w18: R4.2@2510.31,2250 2510,2249.69 2510,2200.31 R63.1@2509.69,2200 R58.2@2545.31,2200
NetR21_2: R21.2 U3.3 | length 86.1
  Top Layer w9: R21.2@2570.31,1980 2572.28,1980 2585.5,1993.22 2585.5,1994.97 2613.15,2022.62 U3.3@2613.15,2047.17
NetR27_2: R27.2 U4.3 | length 86.1
  Top Layer w9: R27.2@2565.31,1160 2567.28,1160 2580.5,1173.22 2580.5,1174.97 2608.15,1202.62 U4.3@2608.15,1227.17
NetR28_2: R28.2 R60.2 R62.1 | length 80.4
  Bottom Layer w18: R62.1@2495,1110 R60.2@2535.31,1110 ; R28.2@2510.31,1150 2510.31,1110.12 2510.43,1110
NetR47_2: R47.2 U6.3 | length 79
  Top Layer w9: R47.2@2570.31,885 2572.28,885 2577.63,890.34 2577.63,892.09 2608.15,922.62 U6.3@2608.15,947.17
NetR58_1: R58.1 U3.9 | length 62.1
  Top Layer w9: v3(2610,2220) 2610,2217.56 2612.73,2214.84 2612.73,2193.26 U3.9@2613.15,2192.83
  Bottom Layer w20: R58.1@2584.69,2200 2586.34,2200 2606.34,2220 v3(2610,2220)
NetR59_1: R59.1 U3.8 | length 60.3
  Top Layer w9: U3.8@2632.83,2192.83 2633.26,2193.26 2633.26,2210.82 2640,2217.56 v3(2640,2220)
  Bottom Layer w18: v3(2640,2220) 2640.31,2220.31 R59.1@2640.31,2250
NetR60_1: R60.1 U6.9 | length 62.9
  Top Layer w9: v3(2605,1120) 2605,1117.56 2607.73,1114.84 2607.73,1093.26 U6.9@2608.15,1092.83
  Bottom Layer w18: R60.1@2574.69,1110 2575.53,1110.84 2595.84,1110.84 v3(2605,1120)
NetR61_1: R61.1 U6.8 | length 76.8
  Top Layer w9: U6.8@2627.83,1092.83 2627.83,1110.4 2640,1122.56 v3(2640,1125)
  Bottom Layer w18: v3(2640,1125) 2640,1136.65 2658.35,1155 R61.1@2660.31,1155
PFM/SYNC1: R15.2 R20.1 TP5.1 U2.16 | length 3291
  Top Layer w8: R20.1@2130,2315.31 R15.2@2170,2315.31 ; v3(2150,2315) 2150,2256.52 2169.55,2236.96 2169.55,2220.88 U2.16@2170.47,2219.96
  Midlayer 4 w10: v3(2150,2315) 2235,2315 2273.78,2353.78 2273.78,2380 2080,2573.78 2080,2785 2285,2990 3275,2990 3420,3135 3420,3218.35 3359.35,3279 2629,3279 TP5.1@2550,3200
PFM/SYNC2: R40.2 R43.1 R45.1 TP11.1 U5.16 | length 3369.8
  Top Layer w8: R45.1@2130,1185.32 2130.16,1185.16 v3@2149.84,1185.16 ; v3@2150,1185.31 R40.2@2170,1185.31 ; v3@2151.84,1183.16 2151.84,1158.64 2169.55,1140.93 2169.55,1120.88 U5.16@2170.47,1119.96 ; v3(2240,2355) 2240.16,2355.16 2240.16,2379.84 R43.1@2240.31,2380
  Midlayer 2 w12: v3(2150,1185) 2071.54,1185 2016.22,1129.68 2016.22,733.78 TP11.1@2550,200
  Midlayer 4 w8: v3(2150,1185) 2150,1260 2184.13,1294.13 2184.13,1970 2155.87,1998.25 2089.3,1998.25 2054.65,2032.91 1935.31,2032.91 1825,2143.22 1825,2299.14 1890.86,2365 1936.22,2365 1975,2326.22 2005,2326.22 2093.78,2415 2214.92,2415 2240,2389.92 v3(2240,2355)
PG/SYNCOUT1: R10.1 R43.2 TP4.1 U2.15 | length 3779.7
  Top Layer w9: v3(2180,2285) 2180.06,2284.94 2180.06,2262.5 2190.08,2252.49 2190.08,2220.04 U2.15@2190.16,2219.96 ; R43.2@2279.69,2380 v3(2305,2380) R10.1@2330.31,2380
  Midlayer 2 w9: v3(2180,2285) 2180,2363.7 2186.37,2370.08 2186.37,2391.35 2191.65,2396.63 2288.37,2396.63 v3(2305,2380)
  Midlayer 4 w9: TP4.1@2150,3200 2246.38,3296.38 3366.54,3296.38 3437.37,3225.55 3437.37,3127.8 3282.2,2972.63 2292.2,2972.63 2097.37,2777.8 2097.37,2587.63 v3(2305,2380)
PG/SYNCOUT2: R35.1 TP10.1 U5.15 | length 1842.7
  Top Layer w9: v3(2185,1155) 2185,1152.56 2190.08,1147.49 2190.08,1120.04 U5.15@2190.16,1119.96 ; v3(2305,1290) R35.1@2330.31,1290
  Midlayer 4 w9: TP10.1@2150,200 2017.45,332.55 2017.45,838.08 2122.25,942.87 2122.25,990.43 2087.47,1025.2 2026.97,1025.2 1999.92,1052.25 1904.52,1052.25 1872.62,1084.14 1872.62,1125.87 1908.13,1161.37 1967.41,1161.37 1995.15,1133.63 2161.19,1133.63 2181.35,1153.78 2185,1153.78 v3(2185,1155) 2186.37,1153.63 2218.85,1153.63 2270,1204.77 2270,1266.47 2292.92,1289.39 2304.39,1289.39 v3(2305,1290)
RT1: R18.1 U2.2 | length 87.6
  Top Layer w9: R18.1@2049.68,2075 2076.02,2075 2091.06,2090.04 U2.2@2131.1,2090.04
RT2: R44.1 U5.2 | length 92.6
  Top Layer w8: R44.1@2044.68,975 2046.65,975 2061.69,990.04 U5.2@2131.1,990.04
SW1: C31.2 C32.2 C35.1 C96.1 D2.2 D4.1 L4.1 L5.1 R11.2 R59.2 U1.4 U1.6 U1.14 U2.12 U3.7 | length 2172.9
  Top Layer w9: U2.12@2268.9,2219.96 2268.9,2226.85 2287.37,2245.33 2287.37,2254.66 2288.58,2255.87 2290.55,2255.87 C32.2@2294.69,2260 v3(2325,2260) ; C96.1@2521,2383.69 2562.53,2383.69 U1.14@2562.95,2383.27 2621.73,2383.27 2630,2375 ; U1.4@2632.83,2327.17 2632.83,2372.17 2630,2375 ; v5(2685,2375.98) 2684.02,2375 2630,2375
  Top Layer w12: v3(1905,2300) 1906.15,2298.85 1928.59,2298.85 R11.2@1937.44,2290
  Top Layer w30: C35.1@2865,1887.56 2865,1949.61 2882.57,1967.18 2887.65,1967.18 2989.37,2068.9 L5.1@2989.37,2250
  Midlayer 2 w12: v3(1905,2300) 1948.78,2300 2095.32,2446.54 2558.46,2446.54 2629.02,2375.98 v5(2685,2375.98) 2685,2355 2649.29,2319.29 2541.94,2319.29 2482.65,2260 v3(2325,2260)
  Bottom Layer w12: v5@2683.66,2374.65 v5(2685,2375.98)
  Bottom Layer w18: D4.1@2324.47,2219 2325,2219.53 v3(2325,2260) ; R59.2@2679.69,2250 2679.69,2294.69 v3(2680,2295) 2680,2296.69 D2.2@2708.31,2325
  other v5: 2685,2331.1 2736.18,2331.1 2787.36,2331.1 2736.18,2375.98 2787.36,2375.98
SW2: C73.2 C74.2 C77.1 C98.1 D6.2 D8.1 L6.1 L7.1 R36.2 R61.2 U4.4 U4.6 U4.14 U5.12 U6.7 | length 2190.5
  Top Layer w9: v3(1905,1190) R36.2@1932.44,1190 ; U5.12@2268.9,1119.96 2269.32,1120.38 2269.32,1133.27 2273.35,1137.3 2273.35,1137.45 2279.91,1144 2292.47,1144 2299.69,1151.22 C74.2@2299.69,1165 v3(2325,1165) ; C98.1@2516,1283.69 2557.53,1283.69 U4.14@2557.95,1283.27 2619.52,1283.27 2627.97,1274.82 ; U4.4@2627.83,1227.17 2627.97,1227.3 2627.97,1274.82 ; v5(2680,1275.98) 2678.84,1274.82 2627.97,1274.82
  Top Layer w20: C77.1@2860,787.56 2860,839.53 2989.37,968.9 L7.1@2989.37,1150
  Midlayer 2 w12: v3(1905,1190) 2058.02,1343.02 2551.98,1343.02 2619.02,1275.98 v5(2680,1275.98) 2680,1248.76 2650.54,1219.29 2546.94,1219.29 2532.13,1204.47 2532.13,1172.13 2525,1165 v3(2325,1165)
  Bottom Layer w12: v5@2676.05,1274.12 2677.92,1275.98 v5(2680,1275.98) ; D6.2@2708.31,1225 D6.2@2709.15,1224.15 ; v3@2709.15,1185.85 v3(2710,1185)
  Bottom Layer w18: v3(2325,1165) 2332.46,1157.54 2332.46,1123.01 D8.1@2341.47,1114 ; R61.2@2699.69,1155 2701.65,1155 2702.5,1155.84 2702.5,1157.81 2710,1165.31 v3(2710,1185) ; v3@2709.15,1185.85 D6.2@2709.15,1224.15
  other v5: 2680,1231.1 2731.18,1231.1 2782.36,1231.1 2731.18,1275.98 2782.36,1275.98
Vbst1: C32.1 D1.1 R63.2 U2.13 | length 414.7
  Top Layer w9: U2.13@2249.21,2219.96 2249.21,2254.66 2254.56,2260 C32.1@2255.31,2260 2255.88,2260 2261.22,2265.34 2261.22,2271.81 2281.69,2292.28 D1.1@2281.69,2320 v3(2305,2320)
  Midlayer 2 w12: v3(2305,2320) 2305,2285.89 2302.13,2283.01 2302.13,2250.53 2315.53,2237.13 2457.57,2237.13 2463.54,2231.15 2468.85,2231.15 v3(2470,2230)
  Bottom Layer w18: v3(2470,2230) 2470.31,2229.69 R63.2@2470.31,2200
Vbst2: C74.1 D5.1 R62.2 U5.13 | length 435.6
  Top Layer w9: U5.13@2249.21,1119.96 2249.63,1120.38 2249.63,1137.45 2258.35,1146.16 2258.35,1163.03 C74.1@2260.31,1165 2260.88,1165 2266.22,1170.34 2266.22,1176.81 2281.69,1192.28 D5.1@2281.69,1230
  Top Layer w12: D5.1@2281.69,1230 v3(2310,1230)
  Midlayer 2 w12: v3(2310,1230) 2310,1200.86 2301.65,1192.51 2301.65,1149.37 2308.9,1142.13 2451.87,1142.13 2457.85,1136.15 2468.85,1136.15 2470,1135
  Bottom Layer w12: v3(2455,1135) v3@2455.16,1134.84 ; R62.2@2455.16,1110.16 R62.2@2455.31,1110
  Bottom Layer w18: R62.2@2455.16,1110.16 v3@2455.16,1134.84
VCC1: C34.1 C50.1 D1.2 R10.2 R21.1 U2.7 | length 1040.3
  Top Layer w9: U2.7@2229.53,2090.04 2229.53,2062.91 2240,2052.44 v3(2240,2050) 2241.72,2048.28 2250.15,2048.28 2267.44,2030.98 C34.1@2267.44,2030 C34.1@2270,2027.44 ; D1.2@2363.31,2320 D1.2@2364.15,2320.85 ; v3@2364.15,2349.15 2365,2350 v3@2364.84,2350.16 ; R10.2@2364.69,2380 R10.2@2364.84,2379.84 ; D1.2@2369.15,2320.85 v3@2369.15,2349.15 ; v3@2369.84,2350.16 R10.2@2369.84,2379.84
  Top Layer w18: v3(2610,1955) 2610,1979.68 R21.1@2609.69,1980 C50.1@2645.31,1980
  Midlayer 2 w12: v3(2370,2350) 2369.5,2350.5 2285,2350.5 2245,2310.5 2245,2210 2270,2185 2270,2130 2240,2100 v3(2240,2050) 2335,1955 v3(2610,1955)
VCC2: C76.1 C92.1 D5.2 R35.2 R47.1 U5.7 | length 961
  Top Layer w9: D5.2@2368.31,1225 2369.15,1225.85 2369.15,1254.15 v3(2370,1255) 2369.84,1255.16 R35.2@2370,1290 ; R35.2@2369.69,1290 R35.2@2369.84,1289.84
  Top Layer w12: R47.1@2609.69,885 R47.1@2609.84,884.84 ; v3@2609.84,860.16 v3(2610,860)
  Top Layer w18: R47.1@2609.69,885 C92.1@2640.31,885 ; v3@2609.84,860.16 R47.1@2609.84,884.84
  Midlayer 2 w12: v3(2370,1255) 2281.24,1255 2255,1228.76 2255,1100.84 2280.54,1075.3 2280.54,990.54 v3(2240,950) 2240.71,950 2330.71,860 v3(2610,860)
VCCX1: C48.2 R7.2 U2.14 | length 2186.4
  Top Layer w9: U2.14@2209.84,2219.96 2209.92,2220.04 2209.92,2274.92 v3(2210,2275) C48.2@2210,2300.31 C48.2@2215,2295.31
  Top Layer w12: v3(3570,2700) R7.2@3605.31,2700
  Midlayer 2 w9: v3@2210,2274.92 v3(2210,2275) v3(2210,2275)
  Midlayer 4 w12: v3(2210,2275) v3(2210,2275) 2227.65,2275 2295.53,2342.87 2313.03,2342.87 2320.65,2350.5 2320.84,2350.5 2327.87,2357.53 2327.87,2472.35 2200,2600.23 2200,2751 2289,2840 2456.71,2840 3430,2840 v3(3570,2700)
VCCX2: C90.2 R31.1 U5.14 | length 2034
  Top Layer w9: U5.14@2209.84,1119.96 2209.92,1120.04 2209.92,1174.92 v3(2210,1175) C90.2@2210,1200.31
  Top Layer w12: v3(3575,1595) R31.1@3605.31,1595
  Midlayer 4 w12: v3(2210,1175) 2242.87,1207.87 2242.87,1434.5 2232.37,1445 2232.37,1661.85 2290.53,1720 3450,1720 v3(3575,1595)
VDDA1: C33.2 R15.1 R19.2 R22.1 U2.6 | length 844.5
  Top Layer w9: v3(2085,1970) R19.2@2085,1995.31 ; v3(2165,2380) 2166.72,2378.28 2166.72,2357.96 R15.1@2170,2354.69 ; U2.6@2209.84,2090.04 2209.92,2089.96 2209.92,2034.76 C33.2@2210,2034.69 2210,2032.72 2215.34,2027.37 2217.09,2027.37 2240,2004.47 R22.1@2240,1969.68 2240.16,1969.84 2264.84,1969.84 v3(2265,1970)
  Midlayer 2 w9: v3(2085,1970) 2085,1993.35 ; v3(2165,2380) 2085,2300 2085,1993.35 ; v3(2265,1970) 2241.65,1993.35 2085,1993.35
VDDA2: C75.2 R40.1 R46.1 R51.1 U5.6 | length 836.4
  Top Layer w8: R40.1@2170,1224.68 2173.09,1227.77 2173.09,1248.09 v3(2175,1250)
  Top Layer w9: v3(2085,870) R46.1@2085,895.32 ; U5.6@2209.84,990.04 U5.6@2209.84,990.04 2209.76,936.18 2209.69,936.1 2209.69,934.13 2215.03,928.79 2216.78,928.79 2240,905.57 R51.1@2240,869.68 2240.16,869.84 2264.84,869.84 v3(2265,870)
  Midlayer 2 w8: v3(2085,870) 2085,893.35 ; v3@2175,1248.76 2175,1180.48 2064.13,1069.61 2064.13,934.13 2085,913.26 2085,893.35 ; v3(2265,870) 2241.65,893.35 2085,893.35
  Midlayer 4 w8: v3@2175,1248.76 2175.45,1249.2 2175,1249.65 v3(2175,1250)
